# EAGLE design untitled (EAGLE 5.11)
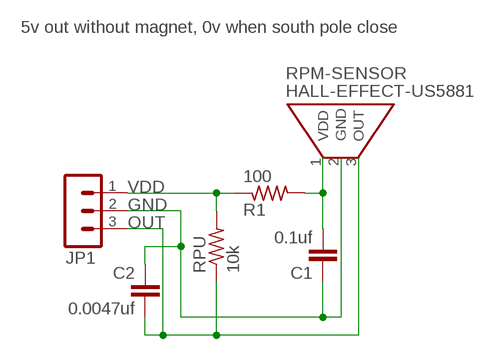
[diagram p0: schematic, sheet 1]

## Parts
C1  0.1uf  C-EU050-024X044  [C050-024X044]
C2  0.0047uf  C-EU050-024X044  [C050-024X044]
JP1  MA03-1  [MA03-1]
R1  100  R-US_0207/10  [0207/10]
RPM-SENSOR  HALL-EFFECT-US5881  [3SIL]
RPU  10k  R-US_0207/10  [0207/10]

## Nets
GND: C1.1 C2.1 JP1.2 RPM-SENSOR.2(GND)
N$1: C1.2 R1.2 RPM-SENSOR.1(VDD)
OUT: C2.2 JP1.3 RPM-SENSOR.3(OUT) RPU.1
VDD: JP1.1 R1.1 RPU.2

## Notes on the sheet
- 5v out without magnet, 0v when south pole close

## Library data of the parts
C1 C2 = rcl:C-EU: CAPACITOR, European symbol
JP1 = con-lstb:MA03-1: PIN HEADER; OC_FARNELL: unknown; OC_NEWARK: unknown
R1 RPU = resistor:R-US_: RESISTOR, American symbol
RPM-SENSOR = trl:HALL-EFFECT-US5881

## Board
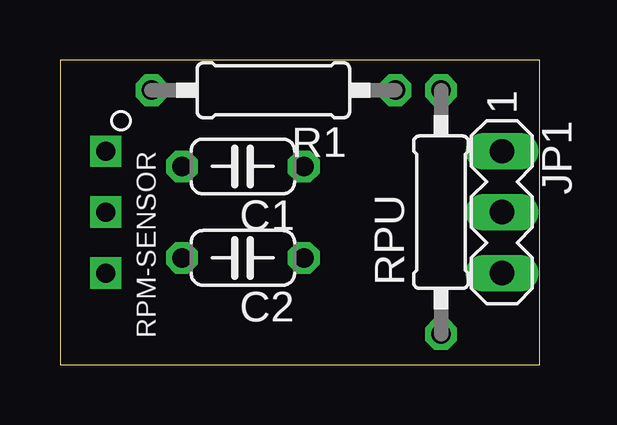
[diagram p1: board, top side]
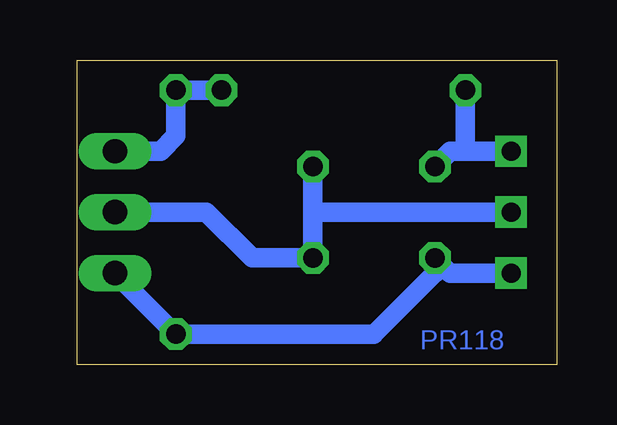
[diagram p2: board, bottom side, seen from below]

Size 19.99 x 12.69 mm. Coordinates in mm from the lower left corner, seen from the top.
Outline: 0,0 19.99,0 19.99,12.69 0,12.69 0,0
Copper layers (1*16): Top 0.035mm / dielectric 1.5mm / Bottom 0.035mm
Design rules "default": minimum track width 10mil, minimum drill 24mil, track to track 8mil, track to pad 8mil, pad to pad 8mil, via to via 8mil, smd to smd 8mil, copper to edge 40mil, drill to drill 8mil, minimum pad ring 10mil, minimum via ring 8mil, stop-mask expansion 4mil, vias tented up to drill 0mil, thermal gap 10mil

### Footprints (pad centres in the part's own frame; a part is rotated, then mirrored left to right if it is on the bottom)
C050-024X044 = drill 0.813 octagon: 1 -2.54,0; 2 2.54,0
MA03-1 = drill 1.016 long: 1 -2.54,0; 2 0,0; 3 2.54,0
0207/10 = drill 0.813 octagon: 1 -5.08,0; 2 5.08,0
3SIL = drill 0.8 square: 1 -2.54,0; 2 0,0; 3 2.54,0

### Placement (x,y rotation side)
C1  7.62,8.26 180 top
C2  7.62,4.45 180 top
JP1  18.41,6.35 270 top
R1  8.89,11.43 180 top
RPM-SENSOR  1.91,6.35 270 top
RPU  15.88,6.35 90 top

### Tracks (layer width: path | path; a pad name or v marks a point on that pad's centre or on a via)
GND
  Bottom 0.813: JP1.2 14.61,6.35 12.7,4.45 C2.1 10.16,6.35 | 10.16,6.35 C1.1 | RPM-SENSOR.2 10.16,6.35
N$1
  Bottom 0.813: RPM-SENSOR.1 3.81,8.89 | 3.81,8.89 4.45,8.89 C1.2 | 3.81,8.89 R1.2
OUT
  Bottom 0.813: RPM-SENSOR.3 4.45,3.81 C2.2 5.08,3.81 7.62,1.27 RPU.1 JP1.3
VDD
  Bottom 0.813: R1.1 RPU.2 15.88,9.53 16.51,8.89 JP1.1

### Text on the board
Bottom: PR118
